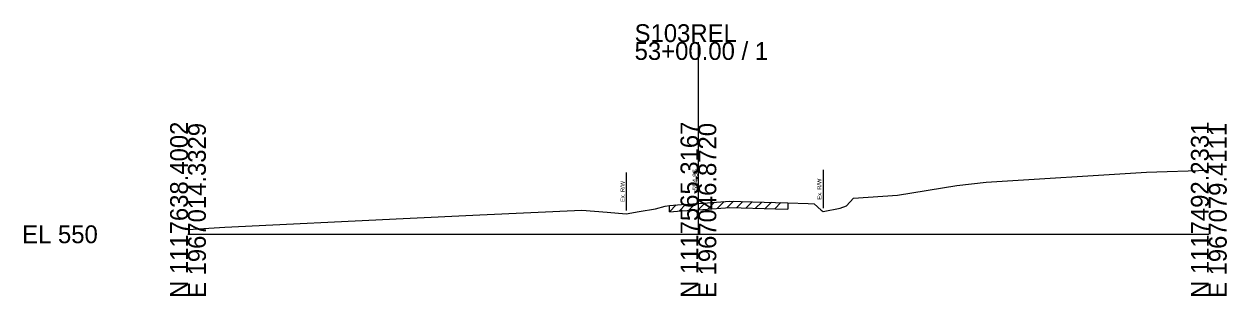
# Model space of a CAD drawing. Extents: x -26 to 163, y -10 to 24518.
# Drawn here: x -25.7 to 162.8, y 3490.3 to 3533 of the extents above; entities that cross this region are included whole.
import ezdxf

# ---------------------------------------------------------------- set-up
doc = ezdxf.new("R2010")
doc.units = 0
for name, color, linetype in [('RD_GPK_XS_Cell', 7, 'Continuous'), ('RD_XS_ExGround', 7, 'Continuous'), ('RD_XS_ExPaveRet', 7, 'Continuous'), ('RD_XS_ExRW', 7, 'Continuous'), ('RD_XS_TX_Elev_EX', 7, 'Continuous')]:
    doc.layers.add(name, color=color, linetype=linetype)

msp = doc.modelspace()

# ---------------------------------------------------------------- linework, layer by layer
at = {"layer": 'RD_GPK_XS_Cell'}
for p, q in [((80, 3500), (80, 3530.19)), ((0, 3500), (80, 3500)), ((80, 3500), (160, 3500))]:
    msp.add_line(p, q, dxfattribs=at)
at = {"layer": 'RD_XS_ExGround'}
msp.add_lwpolyline([(0, 3500.76), (5.8, 3501.14), (33.73, 3502.49), (45.75, 3503.05), (61.73, 3503.79), (65.68, 3503.46), (68.69, 3503.23), (70.74, 3503.58), (73.28, 3504.01), (74.78, 3504.39), (75.46, 3504.51), (77.36, 3504.66), (80, 3504.85), (84.94, 3505.2), (92.09, 3505.01), (94, 3504.96), (97.21, 3504.84), (98.12, 3504.77), (99.22, 3503.78), (99.53, 3503.6), (102.23, 3504.11), (103.2, 3504.49), (104.32, 3505.67), (111.22, 3506.16), (120.51, 3507.64), (125.1, 3508.21), (150.25, 3509.78), (160, 3510.06)], dxfattribs=at)
at = {"layer": 'RD_XS_ExPaveRet'}
for p, q in [((79.96, 3503.84), (81.04, 3504.92)), ((81.46, 3503.95), (82.54, 3505.03)), ((82.96, 3504.06), (84.04, 3505.13)), ((84.46, 3504.16), (85.48, 3505.18)), ((85.96, 3504.17), (86.94, 3505.14)), ((87.46, 3504.13), (88.44, 3505.1)), ((88.96, 3504.09), (89.94, 3505.06)), ((90.46, 3504.05), (91.44, 3505.02)), ((91.96, 3504.01), (92.94, 3504.99)), ((94, 3504.96), (94, 3503.96)), ((75.46, 3503.51), (76.54, 3504.6)), ((75.46, 3503.51), (75.46, 3504.51)), ((75.46, 3503.51), (77.36, 3503.66)), ((76.96, 3503.63), (78.04, 3504.71)), ((77.36, 3503.66), (80, 3503.85)), ((78.46, 3503.74), (79.54, 3504.81)), ((80, 3503.85), (84.94, 3504.2)), ((84.94, 3504.2), (92.09, 3504.01)), ((92.09, 3504.01), (94, 3503.96))]:
    msp.add_line(p, q, dxfattribs=at)
at = {"layer": 'RD_XS_ExRW'}
for p, q in [((68.69, 3509.73), (68.69, 3503.73)), ((99.53, 3510.1), (99.53, 3504.1)), ((99.53, 3510.1), (99.53, 3504.1))]:
    msp.add_line(p, q, dxfattribs=at)

# ---------------------------------------------------------------- texts
at = {"layer": 'RD_GPK_XS_Cell'}
for s, p in [('S103REL', (70, 3530.19)), ('53+00.00 / 1', (70, 3527.39)), ('EL 550', (-26, 3498.6))]:
    msp.add_text(s, height=2.8, dxfattribs=at).set_placement(p)
for s, p in [('N 1117638.4002', (0, 3490)), ('E 1967014.3329', (2.8, 3490)), ('N 1117565.3167', (80, 3490)), ('E 1967046.8720', (82.8, 3490)), ('N 1117492.2331', (160, 3490)), ('E 1967079.4111', (162.8, 3490))]:
    msp.add_text(s, height=2.8, rotation=90, dxfattribs=at).set_placement(p)
at = {"layer": 'RD_XS_ExRW'}
for p in [(99.28, 3505.45), (99.28, 3505.44), (68.44, 3505.08)]:
    msp.add_text('Ex. R/W ', height=0.65, rotation=90, dxfattribs=at).set_placement(p)
at = {"layer": 'RD_XS_TX_Elev_EX'}
msp.add_text('554.85', height=0.8, rotation=90, dxfattribs=at).set_placement((79.9, 3506.85))

doc.saveas('drawing.dxf')
